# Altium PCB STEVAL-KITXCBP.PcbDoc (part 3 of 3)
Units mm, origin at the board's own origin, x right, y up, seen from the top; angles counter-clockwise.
Board outline 265 x 224 mm, 4 copper layers (Top Layer, GND, PWR, Bottom Layer), stack 1.55 mm thick; 241 components, 114 nets, 595 pads, 236 vias.
Unrouted connection lines stored in the file: 2.
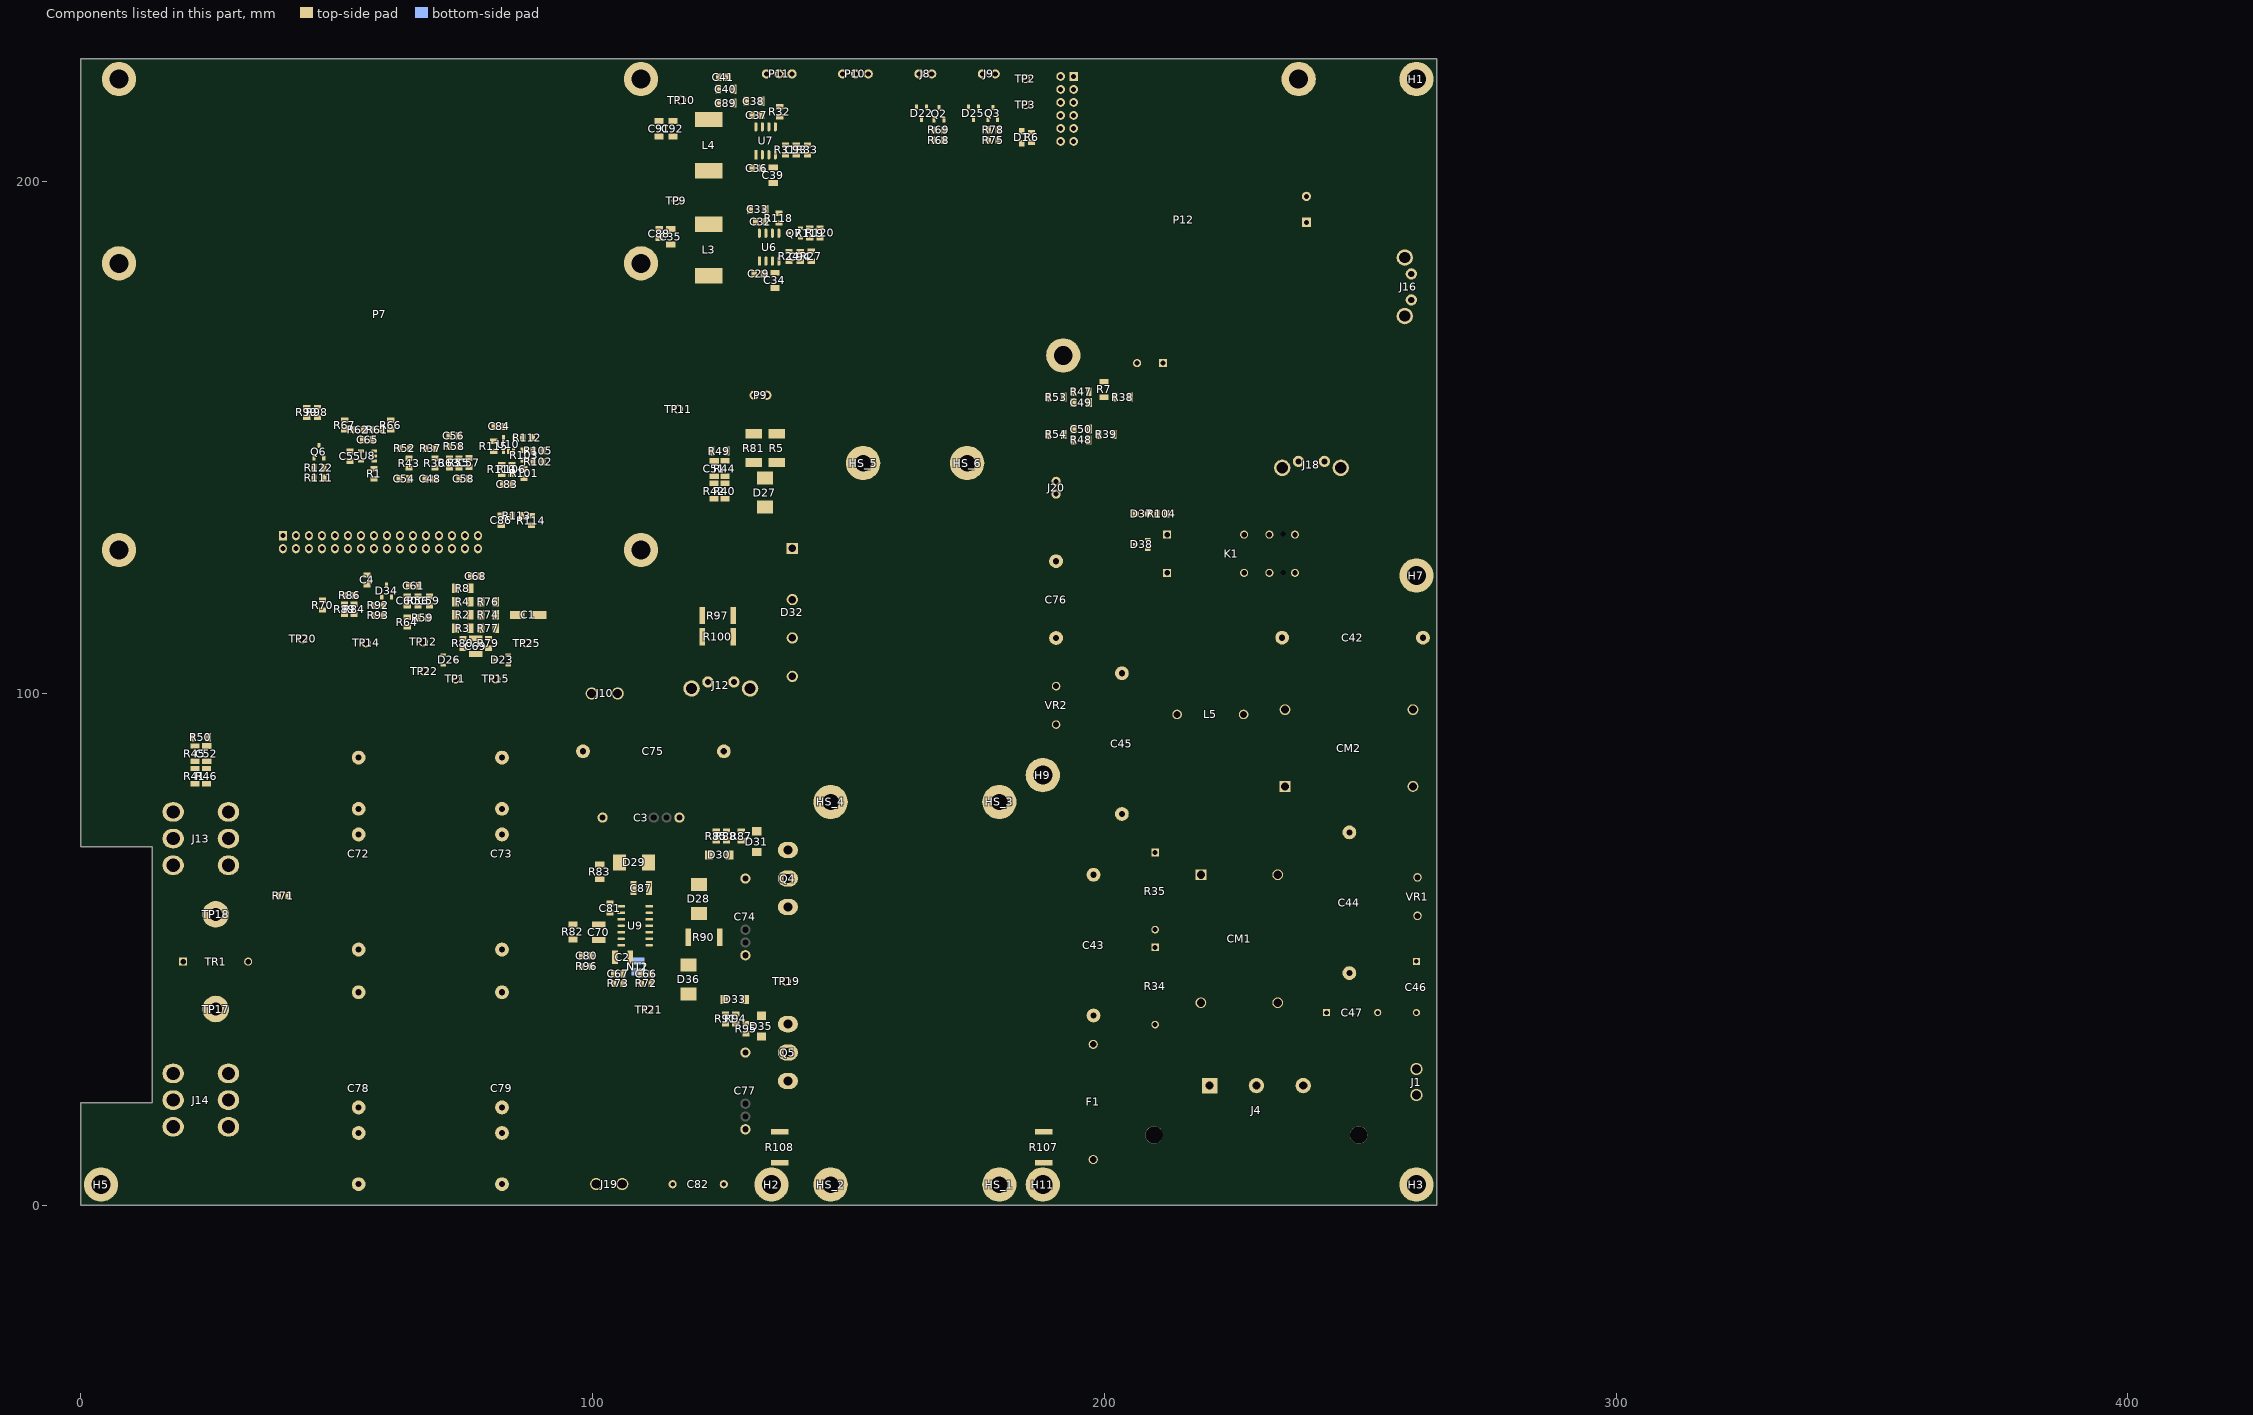
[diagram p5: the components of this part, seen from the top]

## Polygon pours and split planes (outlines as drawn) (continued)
+24V on Top Layer "TOP_LAYER_NONET_P-001" (solid, remove dead copper, pour order 199): 137.983,149.8 138.4,150.217 138.4,153.1 137.9,153.6 134.094,153.6 133.606,153.112 133.606,150.164 133.969,149.8 134.385,149.8
GND on Top Layer "TOP_LAYER_NONET_P-001" (solid, remove dead copper, pour order 197): 98.683,52.378 98.683,50.417 99.2,49.9 102.316,49.9 102.616,50.2 102.616,52.364 102.602,52.378
~Hbridge_ on Top Layer "TOP_LAYER_NONET_P-001" (solid, remove dead copper, pour order 196): 123.68,48.42 123.68,53.759 125.521,55.6 133.1,55.6 133.9,54.8 133.9,47.773 133.127,47 125.1,47
NetC44_2 on Top Layer "NETC44_2_L01_P151" (solid, remove dead copper, pour order 151): 248.339,32.667 249.944,34.272 249.944,39.904 251.077,41.037 255.983,41.037 256.626,41.658 256.626,59.946 258.506,61.826 263.281,61.826 263.942,62.486 263.942,85.245 263.332,85.854 253.88,85.854 251.851,83.825 251.851,69.598 246.06,63.807 231.023,48.77 231.023,33.947 232.304,32.667
~N_open on Top Layer "~N_OPEN_L01_P174" (solid, remove dead copper, pour order 174): 228.976,124.668 224.018,129.626 224.018,151.402 243.582,170.966 262.687,170.966 263.21,171.49 263.21,177.164 262.511,177.864 239.344,177.863 217.15,155.669 217.15,121.239 218.609,119.78 228.618,119.78 228.976,120.138
NetD27_1 on Top Layer "TOP_LAYER_NONET_P-001" (solid, remove dead copper, pour order 193): 129.3,146.7 129.3,141 129.55,140.75 137.95,140.75 138.2,141 138.2,146.7
~PGND on Top Layer "TOP_LAYER_NONET_P-001" (solid, remove dead copper, pour order 192): 115.776,43.2 122.7,43.2 122.9,43 122.9,38.7 122.3,38.1 116.1,38.1 115.6,38.6 115.6,43.024
~DCbus on Top Layer "TOP_LAYER_NONET_P-001" (solid, remove dead copper, pour order 191): 117.6,61.421 118.021,61 131.3,61 131.6,61.3 131.6,65.566 131.154,66.012 118.326,66.012 117.6,65.286
NetC87_1 on Top Layer "TOP_LAYER_NONET_P-001" (solid, remove dead copper, pour order 190): 120.9,44.5 121.3,44.9 121.3,53.759 123.141,55.6 124.1,56.559 124.1,59.406 124.006,59.5 117.8,59.5 114.902,56.602 113.802,56.602 113.249,56.049 113.249,55.651 113.8,55.1 114.652,55.1 116.2,53.552 116.2,44.9 116.6,44.5
~Cap on Top Layer "~CAP_L01_P166" (solid, remove dead copper, pour order 166): 84.5,29.1 86.766,31.366 86.766,50.597 84.379,52.984 51.467,52.984 31.119,32.743 31.105,32.743 28.619,30.256 17.843,30.256 15.08,27.493 15.08,12.789 17.861,10.008 37.107,10.008 56.199,29.1
NetD32_4 on Top Layer "NETD32_4_L01_P172" (solid, remove dead copper, pour order 172): 126,115.797 126,100 127.6,98.4 141.7,98.4 142.232,98.932 142.232,106.261 141.643,106.85 137.889,106.85 135.092,109.647 135.092,116.152 134.244,117 127.203,117
~Hbridge on Top Layer "~HBRIDGE_L01_P177" (solid, remove dead copper, pour order 177): 14.7,80 15.2,80.5 32.4,80.5 33.5,79.4 33.5,55.649 30.228,52.378 16.322,52.378 14.7,54
NetR34_1 on Top Layer "NETR34_1_L01_P161" (solid, remove dead copper, pour order 161): 208.062,56.34 207.858,56.136 207.858,47.978 208.038,47.798 211.892,47.798 211.973,47.878 211.973,56.11 211.743,56.34
~AC_N on Top Layer "~AC_N_L01_P157" (solid, remove dead copper, pour order 157): 187.013,70.8 219.712,70.8 221.219,69.294 221.219,60.754 220.182,59.718 202.319,59.718 193.076,50.475 193.076,28.4 195.514,25.961 223.139,25.961 223.5,25.6 223.5,18.5 223.24,18.24 188.47,18.24 184.643,22.067 184.643,68.43
~AC_L on Top Layer "~AC_L_L01_P150" (solid, remove dead copper, pour order 150): 205.037,39.779 196.886,39.779 195.788,38.681 195.788,30.112 196.891,29.009 203.845,29.009 220.451,29.009 221.778,30.335 221.778,41.404 221.016,42.166 216.444,42.166 214.056,39.779
no net on Top Overlay "TOP_LAYER_NONET_P-001" (hatched 45Degree grid 2.54 track 0.4): 142.98,0.017 142.98,150.017 182.98,150.017 182.98,0.017
GND on Bottom Layer "TOP_LAYER_NONET_P-001" (solid, remove dead copper, pour order 188): 199.6,222 198.145,223.455 4.355,223.455 1.5,220.6 1.5,95.1 3.8,92.8 28.2,92.8 35.1,85.9 35.1,61.178 41.278,55 85.93,55 100.13,40.8 112.638,40.8 113.005,41.167 113.005,45.716 112.621,46.1 104.476,46.1 103.657,46.919 103.657,50.976 104.435,51.754 106.684,51.754 107.954,53.024 107.954,58.843 102.197,64.6 50.85,64.6 48.7,66.75 48.7,95.9 50.4,97.6 79.4,97.6 121.984,140.184 153.395,140.184 199.6,186.389
~Neutral on Bottom Layer "~NEUTRAL_L04_P162" (solid, remove dead copper, pour order 162): 244.6,166.4 211.1,166.4 210.7,166 210.7,159.5 213.66,156.54 238.679,156.54 240.574,154.625 240.574,130.287 235.572,125.286 235.572,121.645 233.462,119.535 225.994,119.535 203.49,97.03 187.989,97.03 187.637,96.678 187.637,91.496 188.3,90.833 194.172,90.833 196.835,88.17 196.835,74.446 197.953,73.327 221.189,73.327 223.556,75.694 223.556,87.734 226.299,90.477 247.33,90.477 251.968,95.752 251.968,155.499 251.968,159.032
+24V on Bottom Layer "TOP_LAYER_NONET_P-001" (solid, remove dead copper, pour order 186): 109.7,208.8 106.1,205.2 70.3,205.2 39.53,174.43 39.53,131.095 40.493,130.132 40.915,129.71 40.915,127.253 39.262,125.6 33.276,125.6 28.5,130.376 28.5,176.7 67.4,215.6 108.8,215.6 109.7,214.7
+16V on Bottom Layer "+16V_L04_P170" (solid, remove dead copper, pour order 170): 140.411,194.361 140.411,203.51 139.499,204.368 70.668,204.368 40.28,173.98 40.28,123.897 40.492,123.7 48.09,123.7 49.073,124.683 49.073,165.132 69.518,185.776 138.871,185.776 139.192,186.097 139.192,193.142
~DCbus on Bottom Layer "~DCBUS_L04_P165" (solid, remove dead copper, pour order 165): 123.9,121 135.465,121 141.6,127.135 141.6,138 140.9,138.7 122.848,138.7 114.994,130.846 85.7,101.552 80.248,96.1 51.1,96.1 50.2,95.2 50.2,67.473 51.573,66.1 102.852,66.1 107.552,61.4 160.1,61.4 160.8,62.1 160.8,88.4 157.5,91.7 128.1,91.7 123.9,95.9
~PGND on Bottom Layer "TOP_LAYER_NONET_P-001" (solid, remove dead copper, pour order 189): 16.791,53.991 14,51.2 14,0.647 156.847,0.647 161.3,5.1 161.3,58.6 160.1,59.8 109.362,59.8 108.9,59.338 108.9,52.932 106.848,50.881 103.921,50.881 103.786,50.745 103.786,47.424 105.11,46.1 112.621,46.1 113.005,45.716 113.005,41.698 112.107,40.8 100.17,40.8 86.979,53.991
+16V on Bottom Layer "TOP_LAYER_NONET_P-001" (solid, remove dead copper, pour order 185): 96.3,53.508 96.3,50.308 95.976,49.984 94.324,49.984 93.947,50.362 93.947,53.455 94.3,53.808 96,53.808
NetC44_2 on Bottom Layer "NETC44_2_L04_P156" (solid, remove dead copper, pour order 156): 259.903,85.854 263.332,85.854 263.942,85.245 263.942,62.461 262.837,61.356 259.001,61.356 254.976,65.382 254.976,80.927
~AC_N on Bottom Layer "~AC_N_L04_P168" (solid, remove dead copper, pour order 168): 187.013,70.8 219.712,70.8 221.219,69.294 221.219,60.754 220.182,59.718 202.319,59.718 193.076,50.475 193.076,28.4 195.514,25.961 223.139,25.961 223.5,25.6 223.5,18.5 223.24,18.24 188.47,18.24 184.643,22.067 184.643,68.43
~AC_L on Bottom Layer "~AC_L_L04_P158" (solid, remove dead copper, pour order 158): 205.037,39.779 196.886,39.779 195.725,38.618 195.725,30.175 196.891,29.009 203.845,29.009 220.599,29.009 221.778,30.188 221.778,41.404 221.016,42.166 216.444,42.166 214.056,39.779
NetC44_1 on Bottom Layer "NETC44_1_L04_P155" (solid, remove dead copper, pour order 155): 230.922,85.753 230.414,85.245 230.414,56.594 232.446,54.562 251.953,54.562 255.356,51.158 255.356,44.13 256.304,43.182 263.281,43.182 264.163,44.064 264.163,60.03 263.789,60.404 258.072,60.404 251.953,66.523 251.953,83.619 249.768,85.804 249.718,85.753
NetC44_2 on Bottom Layer "NETC44_2_L04_P152" (solid, remove dead copper, pour order 152): 231.023,44.148 231.023,33.947 232.304,32.667 245.473,32.667 246.822,34.016 246.822,38.915 248.944,41.037 251.75,43.843 251.75,47.246 250.073,48.923 235.798,48.923
+24V on PWR "+24V_L03_P171" (solid, remove dead copper, pour order 171): 197.844,223.456 199.4,221.9 199.4,187.2 161.4,149.2 132.486,149.2 132.486,218.084 133.045,218.643 154.689,218.643 159.502,223.456
~Line on PWR "~LINE_L03_P164" (solid, remove dead copper, pour order 164): 200.33,106.682 203.075,109.428 203.075,128.989 203.075,165.275 204.1,166.3 207.1,166.3 207.1,161 218.177,149.923 239.777,149.923 240.574,149.126 240.574,129.067 239.899,128.393 232.193,128.393 217.612,113.812 217.612,92.204 215.631,90.223 210.094,90.223 202.677,97.64 188.961,97.64 187.894,98.707 187.894,105.463 189.113,106.682
+3V3 on PWR "TOP_LAYER_NONET_P-001" (solid, remove dead copper, pour order 183): 46.62,100.68 48.9,98.4 79.05,98.4 92.763,112.113 92.763,153.453 90.216,156 51.446,156 46.62,151.174
+5V on PWR "+5V_L03_P175" (solid, remove dead copper, pour order 175): 28.575,133.615 38.087,124.102 43.876,124.102 46.051,126.277 46.051,132.649 36.746,141.954 36.746,161.996 76.55,201.8 115.454,201.8 124.037,210.383 124.037,220.248 123.242,221.043 116.576,221.043 107.065,211.533 71.322,211.533 28.575,168.786
+3V3 on PWR "TOP_LAYER_NONET_P-001" (solid, remove dead copper, pour order 184): 131.73,220.232 133.318,218.643 151.62,218.643 152.034,219.058 152.034,222.9 151.465,223.469 133.232,223.469 131.73,221.967
~Hbridge_ on PWR "TOP_LAYER_NONET_P-001" (solid, remove dead copper, pour order 194): 22.5,45.1 20.831,43.431 20.831,32.369 22.2,31 30.154,31 33.3,27.854 33.3,21.6 36.934,17.966 149.066,17.966 152.2,21.1 152.2,56.4 148,60.6 125.6,60.6 122.311,57.311 122.311,41.168 118.243,37.1 98.5,37.1 90.5,45.1
~AC_N on PWR "~AC_N_L03_P167" (solid, remove dead copper, pour order 167): 187.013,70.8 219.712,70.8 221.219,69.294 221.219,60.754 220.182,59.718 202.319,59.718 193.076,50.475 193.076,28.4 195.514,25.961 223.139,25.961 223.5,25.6 223.5,18.5 223.24,18.24 188.47,18.24 184.643,22.067 184.643,68.43
~Line_pf on PWR "~LINE_PF_L03_P163" (solid, remove dead copper, pour order 163): 262.164,88.394 264.95,91.181 264.95,112.989 261.3,116.639 224.622,116.639 221.066,113.083 221.066,90.426 223.098,88.394
~AC_L on PWR "~AC_L_L03_P159" (solid, remove dead copper, pour order 159): 205.037,39.779 196.886,39.779 195.725,38.618 195.725,30.175 196.891,29.009 203.845,29.009 220.482,29.009 221.778,30.305 221.778,41.404 221.016,42.166 216.444,42.166 214.056,39.779
NetC44_2 on PWR "NETC44_2_L03_P154" (solid, remove dead copper, pour order 154): 248.339,32.667 249.944,34.272 249.944,39.904 251.077,41.037 255.983,41.037 256.626,41.658 256.626,59.946 258.506,61.826 263.281,61.826 263.942,62.486 263.942,85.245 263.332,85.854 253.88,85.854 251.851,83.825 251.851,69.598 246.06,63.807 231.023,48.77 231.023,33.947 232.304,32.667

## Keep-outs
GND:
  circle w0.1: c109.5,128 r4.4
  circle w0.1: c146.543,4 r4.45
Bottom Layer:
  lines w0.1: 106.578,124.71 cw(c109.5,128) 112.923,130.764
Keep-Out Layer:
  circle w0.1: c7.5,220 r4.45
  circle w0.1: c109.5,220 r4.45
  circle w0.1: c109.5,184 r4.45
  circle w0.1: c7.5,128 r4.45
  circle w0.1: c7.5,184 r4.45
  circle w0.1: c146.543,78.753 r4.45
  circle w0.1: c152.893,144.965 r4.45

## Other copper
Top Layer:
  rectangle net ~Hbridge_: 124.391,54 125.8,54.343
  rectangle net ~Hbridge_: 123.68,50.2 125.8,54.058
  rectangle net ~PGND: 116.7,39.5 120.9,43
  rectangle net NetC87_1: 116.8,45.2 120.8,48.6
  rectangle net NetC87_1: 117.8,50.2 119.7,54.4
  rectangle net NetC87_1: 118.8,55.3 122.8,58.7
  rectangle net ~DCbus: 118.8,61 122.8,64.3
  region net NetD32_4: 125.543,108.427 129.526,108.427 131.133,110.034 131.133,116.409 130.541,117 125.848,117 125.543,116.695
  pour cut-out: 132.819,183.324 132.819,183.093 132.799,183.073 132.875,183.073 132.916,183.114 132.916,183.139
  region: 416.329,194.47 416.329,194.267 416.126,194.267 416.126,194.47 416.126,194.673 416.329,194.673
  region net ~PGND: 123.601,118.532 120.228,118.532 118,116.304 118,108.258 118.569,107.688 123.601,107.688
  region net HS_2: 149.737,2.084 148.469,0.817 141.615,0.817 141,1.431 141,10.843 138.315,13.528 134.9,13.528 134.9,14.9 143.534,14.9 149.737,8.698
  region net PE03: 123.157,8.4 122.462,7.705 122.462,1.184 123.106,0.54 136.725,0.54 138.3,2.115 138.3,7.7 137.6,8.4
  region net HS_1: 176.06,1.473 176.718,0.815 182.532,0.815 182.791,1.074 182.791,11.269 184.895,13.374 189.848,13.374 189.848,14.846 179.776,14.846 176.06,11.13
  region net PE03: 186.198,8.782 184.904,7.489 184.904,1.791 186.018,0.677 190.082,0.677 191.129,1.725 191.129,7.607 189.955,8.782
  text ".layer_name" at 90.889,-24.229 h1.52
GND:
  rectangle net ~PGND: 106.379,47.113 111.74,49.372
  rectangle net GND: 106.379,44.252 112.621,46.1
  region net NetC76_2: 228.11,118.365 230.886,121.14 230.886,124.333 231.135,124.582 233.462,124.582 233.771,124.272 233.771,115.537 231.813,113.579 231.428,113.579 228.247,116.76
  text ".layer_name" at 91.625,-23.739 h1.52
PWR:
  text ".layer_name" at 91.872,-23.617 h1.52
Bottom Layer:
  rectangle net GND: 107.423,44.4 110.2,44.874
  rectangle net ~PGND: 106.023,47.113 112.621,48.9
  rectangle net GND: 106.023,44.4 112.621,46.1
  pour cut-out: 136.086,121 120.002,121 116.4,117.398 116.4,107.9 118.1,106.2 133.952,106.2 136.086,108.334 136.086,114.816
  region net +24V: 137.282,218.364 132.875,218.364 132.687,218.176 132.687,215.952 133.166,215.473 137.602,215.473 137.81,215.682 137.81,218.055 137.502,218.364
  region net NetC76_1: 226.979,137.724 225.323,137.724 225.323,141.303 227.676,143.655 229.458,143.655 233.771,139.341 233.771,130.241 233.462,129.931 231.135,129.931 230.886,130.18 230.886,133.817
  text ".layer_name" at 92.24,-24.354 h1.52

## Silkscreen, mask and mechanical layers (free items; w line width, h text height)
Top Overlay:
  drawing of 79 lines, arcs and shapes, not listed
  text "GND" at 142.469,220.1 h0.64 r90
  text "GND" at 195.434,219.972 h0.76
  text "+3V3" at 131.3,219.342 h0.64 r90
  text "+24V" at 195.434,217.382 h0.76
  text "GND" at 154.61,215 h0.76 r90
  text "+24V" at 195.434,214.842 h0.76
  text "+3V3" at 149.394,214.8 h0.64 r90
  text "GND" at 189.792,213.387 h0.76 r90
  text "+24V" at 195.434,212.302 h0.76
  text "+24V" at 195.434,209.812 h0.76
  text "GND" at 195.8,207.272 h0.76
  text "WARNING!" at 163.413,192.759 h2
  text "J" at 257,192.1 h15.24 r90
  text "STEVAL-KiTXCBP / STEVAL$KiTXCBPA" at 262.9,191.6 h2.6 r90
  text "HIGH VOLTAGE" at 162.065,191.073 h1.8
  text "ON BOARD" at 163.785,189.573 h1.8
  text "~L_OPEN" at 249.3,182.3 h0.76
  text "~N_OPEN" at 249.6,174.8 h0.76
  text "Temp. sensor" at 128.4,161.8 h0.76
  text "~LINE" at 207.08,156.893 h0.76 r90
  text "~NEUTRAL" at 212.16,155.742 h0.76 r90
  text "~LINE" at 238.4,150.4 h0.76 r90
  text "~NEUTRAL" at 243.6,150.3 h0.76 r90
  text "FOR EVALUATION ONLY" at 259.651,142.135 h1.14 r90
  text "NOT FCC APPROVED" at 261.548,142.135 h1.14 r90
  text "FOR RESALE" at 263.41,142.135 h1.14 r90
  text "I" at 262.2,136.4 h7.62 r90
  text "GND" at 42.333,132.534 h0.76
  text "TempSens2" at 63.098,132.455 h0.64 r90
  text "Heatsink" at 64.93,132.455 h0.64 r90
  text "Temp_p" at 65.948,132.451 h0.64 r90
  text "PWM_1L*" at 52.717,132.427 h0.64 r90
  text "pwm_en/SD*" at 55.169,132.441 h0.64 r90
  text "Zero-X" at 57.841,132.427 h0.76 r90
  text "GND" at 60.244,132.441 h0.76 r90
  text "PWM_1H" at 50.295,132.424 h0.64 r90
  text "UDCp" at 68.22,132.402 h0.64 r90
  text "IDCp" at 70.541,132.402 h0.64 r90
  text "IACp" at 73.081,132.402 h0.64 r90
  text "GND" at 78.161,132.402 h0.76 r90
  text "GND" at 75.391,132.272 h0.76 r90
  text "dge" at 68.496,124.892 h0.64 r90
  text "GND" at 75.621,124.691 h0.76 r90
  text "Fan1" at 49.805,124.577 h0.64 r90
  text "PWM" at 50.635,124.589 h0.64 r90
  text "GND" at 78.199,124.559 h0.76 r90
  text "Ubri" at 67.473,124.518 h0.64 r90
  text "IDCn" at 70.406,124.45 h0.64 r90
  text "En" at 58.682,124.435 h0.76 r90
  text "GND" at 60.6,124.435 h0.76 r90
  text "16V" at 57.752,124.402 h0.76 r90
  text "+24V" at 39.908,124.376 h0.64 r90
  text "PWM" at 53.383,124.389 h0.64 r90
  text "LINE" at 55.352,124.376 h0.64 r90
  text "Sen3" at 63.401,124.384 h0.64 r90
  text "Fan2" at 52.554,124.364 h0.64 r90
  text "Temp" at 62.657,124.319 h0.64 r90
  text "+16V" at 42.675,124.273 h0.64 r90
  text "+5V" at 45.212,124.273 h0.64 r90
  text "+3V3" at 47.752,124.273 h0.64 r90
  text "en" at 55.969,124.285 h0.64 r90
  text "Ucap" at 65.512,124.247 h0.64 r90
  text "IACn" at 73.132,124.227 h0.64 r90
  text "Ubridge" at 62,107.2 h0.76
  text "Zero-X" at 53.4,107.1 h0.76
  text "IDCp" at 62.7,102.5 h0.76
  text "DCbus" at 114.9,100.422 h0.76 r90
  text "DCbus" at 94.074,98.352 h0.76
  text "WARNING" at 133.63,81.723 h1.5
  text "WARNING" at 186.23,69.523 h1.5
  text "~Hbridge" at 29.723,55.107 h0.76
  text "~Hbridge_" at 30.379,36.525 h0.76
  text "PGND" at 109.576,35 h0.76
  text "~Cap" at 21.288,27.427 h0.76
  text "PE" at 257.297,22.215 h0.76
  text "PGND" at 101.674,5.812 h0.76
  text "PGND" at 117.307,3.32 h0.76
  text ".layer_name" at 91.633,-22.735 h1.52
Bottom Overlay:
  text ".layer_name" at 91.981,-22.824 h1.52
Top Paste:
  text ".layer_name" at 92.332,-22.651 h1.52
Bottom Paste:
  text ".layer_name" at 92.098,-22.904 h1.52
Top Solder:
  text ".layer_name" at 92.565,-22.651 h1.52
Bottom Solder:
  text ".layer_name" at 92.098,-22.904 h1.52
Drill Guide:
  text ".layer_name" at 92.019,-23.059 h1.52
M1 Board Outline:
  lines w0.1: 170.037,217.6 175.037,217.6
  lines w0.254: 0,0 0,20 14,20 14,70 0,70 0,224 265,224 265,0 0,0
  text ".layer_name" at 91.638,-22.78 h1.52
M2 Board Dimensions:
  text ".layer_name" at 92.001,-22.833 h1.52
M9 Title Sheet:
  lines w0.2: 83.259,281.275 113.009,281.275 ; 229.495,261.582 262.995,261.582 ; 82.259,249.275 227.009,249.275 227.009,284.775 220.759,284.775 82.259,284.775 82.259,255.525 82.259,249.275 ; 83.009,250.525 85.509,250.525 85.509,253.025 83.009,253.025 83.009,250.525 ; 83.009,259.525 85.509,259.525 85.509,262.025 83.009,262.025 83.009,259.525 ; 121.508,256.179 124.008,256.179 124.008,258.679 121.508,258.679 121.508,256.179 ; 121.509,259.525 124.009,259.525 124.009,262.025 121.509,262.025 121.509,259.525 ; 121.509,262.525 124.009,262.525 124.009,265.025 121.509,265.025 121.509,262.525 ; 121.509,265.525 124.009,265.525 124.009,268.025 121.509,268.025 121.509,265.525 ; 121.509,268.525 124.009,268.525 124.009,271.025 121.509,271.025 121.509,268.525 ; 121.509,271.525 124.009,271.525 124.009,274.025 121.509,274.025 121.509,271.525 ; 138.008,256.179 140.508,256.179 140.508,258.679 138.008,258.679 138.008,256.179 ; 138.009,259.525 140.509,259.525 140.509,262.025 138.009,262.025 138.009,259.525 ; 138.009,262.525 140.509,262.525 140.509,265.025 138.009,265.025 138.009,262.525 ; 138.009,265.525 140.509,265.525 140.509,268.025 138.009,268.025 138.009,265.525 ; 138.009,268.525 140.509,268.525 140.509,271.025 138.009,271.025 138.009,268.525 ; 138.009,271.525 140.509,271.525 140.509,274.025 138.009,274.025 138.009,271.525 ; 156.259,268.525 158.759,268.525 158.759,271.025 156.259,271.025 156.259,268.525 ; 156.259,271.525 158.759,271.525 158.759,274.025 156.259,274.025 156.259,271.525 ; 172.259,262.525 174.759,262.525 174.759,265.025 172.259,265.025 172.259,262.525 ; 172.259,265.525 174.759,265.525 174.759,268.025 172.259,268.025 172.259,265.525 ; 172.259,268.525 174.759,268.525 174.759,271.025 172.259,271.025 172.259,268.525 ; 172.259,271.525 174.759,271.525 174.759,274.025 172.259,274.025 172.259,271.525 ; 229.495,249.607 262.995,249.607 262.995,265.582 229.495,265.582 229.495,249.607
  text "PCB SPECIFICATIONS :" at 83.259,281.775 h3
  text "A.   MATERIAL :" at 83.259,277.775 h3
  text "FR-4 HIGH TG" at 121.759,277.775 h3
  text "B.   MATERIAL FAMILY :" at 83.259,274.775 h3
  text "N/A" at 121.759,274.775 h3
  text "x   GREEN" at 121.959,272.008 h3
  text "WHITE" at 141.687,271.827 h3
  text "C.   SOLDERMASK COLOR :" at 83.259,271.775 h3
  text "BLUE" at 156.509,271.775 h3
  text "BLACK" at 172.509,271.775 h3
  text "D.   SILKSCREEN COLOR :" at 83.259,268.775 h3
  text "X  WHITE" at 121.759,268.775 h3
  text "YELLOW" at 138.259,268.775 h3
  text "BLACK" at 156.509,268.775 h3
  text "Blue ink PANTONE 2955" at 172.509,268.775 h3
  text "E.   SURFACE FINISH :" at 83.259,265.775 h3
  text "X  ENIG" at 121.759,265.775 h3
  text "IMMERSION SILVER" at 138.259,265.775 h3
  text "IMMERSION TIN" at 172.509,265.775 h3
  text "HASL" at 121.759,262.775 h3
  text "HASL (PB-FREE)" at 138.259,262.775 h3
  text "GOLDEN FINGER" at 172.509,262.775 h3
  text "MINIMUM PARAMETERS" at 230.745,262.332 h3
  text "F.   IMPEDANCE CONTROL :" at 83.259,259.775 h3
  text "X  NO" at 121.759,259.775 h3
  text "YES  (SEE IMPEDANCE TABLE FOR DETAIL INFORMATION)" at 138.259,259.775 h3
  text "DEFAULT" at 230.745,256.832 h3
  text "G.   VIA TENTING :" at 83.259,256.775 h3
  text "YES" at 141.263,256.54 h3
  text "X  NO" at 121.86,256.397 h3
  text "TRACKS : 0.381mm           /  GAPS     : 0.229mm" at 230.745,251.082 h3
  text "H.   STACK-UP :" at 83.259,250.775 h3
  text "SEE LAYER STACK-UP SEQUENCE FOR OVERALL THICKNESS." at 121.759,250.775 h3
  text ".layer_name" at 91.948,-22.833 h1.52
M10 Fab Notes:
  text "FAB NOTES:" at 276.007,49.398 h1.27
  text "1) ALL CORE AND PREPREG THICKNESSES ARE UP TO FAB SHOP TO SELECT." at 282.913,45.857 h1.27
  text "2)ALL VIAS ARE  NON TENTED" at 282.913,43.132 h1.27
  text "3)VENDOR MAY ADJUST SOLDERMASK WHEREVER SOLDERMASK PADS ARE SAME SIZE(1:1)" at 282.913,40.611 h1.27
  text "AS PER MANUFACTURING CAPABILITIES AND ALL OTHER SOLDERMASK PADS SHALL NOT BE MODIFIED" at 285.394,37.741 h1.27
  text "PROVIDED NO ADJACENT COPPER IS EXPOSED AND NO CONFLICT PRODUCED WITH ANY STATED" at 285.394,35.176 h1.27
  text "\"VIA TENTING/COVERING\" REQUIREMENTS." at 285.394,32.813 h1.27
  text "4)THIS IS NOT AN IMPEDANCE CONTROLLED BOARD" at 282.913,29.816 h1.27
  text "5)BOARD THICKNESS IS 1.6MM +/- 10% TOLERANCE" at 282.913,27.636 h1.27
  text "6)ALL FABRICATION ITEM MUST MEET OR EXCEED BEST INDUSTRY PRACTICE. IPC-A-600C (Commercial Std.)" at 282.913,25.456 h1.27
  text "7)MINIMUM COPPER WALL THICKNESS OF PLATED-THRU   HOLES TO BE 0.001 INCH, WITH A MINIMUM ANNULAR RING OF 0.002 INCH" at 282.913,23.275 h1.27
  text "8)MAX. WARP & TWIST TO BE .0075 INCHES PER INCH" at 282.913,21.095 h1.27
  text "9)HOLE POSITIONAL TOLERANCE ACCURACY IS  +/- 3 MILS" at 282.913,18.915 h1.27
  text "10)SOLDERMASK BOTH SIDES PER ARTWORK.GREEN LPI" at 282.913,16.734 h1.27
  text "11)SILKSCREEN BOTH SIDES PER ARTWORK.COLOR=WHITE." at 282.913,14.757 h1.27
  text "12)DIELECTRIC MATERIAL: FR4-HIGH TG" at 282.913,12.634 h1.27
  text ".layer_name" at 92.311,-22.833 h1.52
M11 Gerber Information:
  circle w0.254: c169.089,-30.052 r1.3
  region: 154.611,-31.146 143.855,-31.146 144.848,-28.653 152.706,-28.653 153.154,-27.893 155.363,-30.442
  region: 168.614,-22.816 153.087,-22.816 152.392,-24.591 151.182,-25.816 149.785,-23.956 149.785,-22.305 150.928,-20.908 152.364,-20.53 168.614,-20.53
  lines w0.254: 144.848,-28.653 153.64,-28.653 150.574,-25.115 cw(c152.378,-23.171) 152.618,-20.53 169.382,-20.53 168.62,-22.816 ; 148.162,-20.283 cw(c150.588,-21.253) 150.824,-18.651 ; 148.201,-20.25 143.855,-31.146 163.177,-31.146 ccw(c163.426,-28.411) 165.975,-29.431 ; 149.941,-24.185 155.363,-30.442 ; 150.195,-24.185 155.5,-30.306 ; 150.195,-23.931 155.5,-30.052 ; 150.293,-22.816 163.286,-22.816 ; 150.322,-23.804 155.627,-29.925 ; 150.449,-23.677 155.754,-29.798 ; 150.576,-23.55 155.881,-29.671 ; 150.703,-23.423 156.008,-29.544 ; 150.757,-21.471 156.062,-27.592 ; 150.826,-18.651 170.275,-18.651 165.976,-29.428 ; 150.83,-23.296 156.08,-29.354 ; 150.83,-23.042 156.135,-29.163 ; 150.83,-22.788 156.135,-28.909 ; 150.83,-21.899 156.135,-28.02 ; 150.957,-22.661 156.262,-28.782 ; 150.957,-22.28 156.262,-28.401 ; 152.328,-28.666 ccw(c152.433,-28.131) 152.731,-27.674 ; 153.415,-22.803 ccw(c153.389,-23.37) 153.059,-23.832 155.423,-26.561 cw(c153.62,-28.505) 154.352,-31.053 ; 159.696,-30.941 162.586,-22.562 ; 159.919,-30.892 162.788,-22.571 ; 160.046,-30.892 162.915,-22.571 ; 160.3,-30.892 163.169,-22.571 ; 160.554,-30.892 163.423,-22.571 ; 160.808,-30.892 163.677,-22.571 ; 161.062,-30.892 163.931,-22.571 ; 161.316,-30.892 164.185,-22.571 ; 161.57,-30.892 164.439,-22.571 ; 161.824,-30.892 164.693,-22.571 ; 162.032,-30.941 164.922,-22.562 ; 164.922,-22.816 168.614,-22.816 ; 167.946,-22.813 168.708,-20.527 ; 168.112,-22.816 168.874,-20.53 ; 168.366,-22.816 169.128,-20.53
  lines w0.3: 82.084,-35.032 172.084,-35.032 172.084,-15.032 82.084,-15.032 ; 82.084,-30.032 142.084,-30.032 ; 82.084,-25.032 142.084,-25.032 ; 82.084,-20.032 142.084,-20.032 ; 82.085,-35.032 82.085,-15.032 ; 122.084,-35.032 122.084,-20.032 ; 142.084,-35.032 142.084,-15.032 ; 159.696,-30.941 162.032,-30.941
  text "Project: POWER STAGE BOARD" at 83.085,-18.248 h3
  text "Layer:" at 83.085,-23.332 h3
  text ".layer_name" at 90.302,-23.381 h1.52
  text "Variant: '.VariantName'" at 83.085,-28.332 h3
  text "R" at 168.581,-30.814 h1.52
  text "YEAR: 2022" at 83.085,-33.332 h3
  text "Rev: A" at 123.143,-33.332 h3
M12 Stackup:
  drawing of 307 lines, arcs and shapes, not listed
  text "Layer" at 285.381,217.978 h1.52
  text "Name" at 295.793,217.978 h1.52
  text "Material" at 319.408,217.978 h1.52
  text "Thickness" at 341.246,217.978 h1.52
  text "Constant" at 357.752,217.978 h1.52
  text "Board Layer Stack" at 372.227,217.978 h1.52
  text "Top Overlay" at 295.793,214.93 h1.52
  text "Top Solder" at 295.793,211.882 h1.52
  text "Solder Resist" at 319.408,211.882 h1.52
  text "0.40mil" at 341.246,211.882 h1.52
  text "3.5" at 357.752,211.882 h1.52
  text "1" at 285.381,208.834 h1.52
  text "Top Layer" at 295.793,208.834 h1.52
  text "COPPER" at 319.408,208.834 h1.52
  text "2.76mil" at 341.246,208.834 h1.52
  text "2oz(70um)" at 407.837,208.845 h1.27
  text "Dielectric 1" at 295.793,205.786 h1.52
  text "FR-4 HIGH TG" at 319.408,205.786 h1.52
  text "15.00mil" at 341.246,205.786 h1.52
  text "4.2" at 357.752,205.786 h1.52
  text "2" at 285.381,202.738 h1.52
  text "GND" at 295.793,202.738 h1.52
  text "COPPER" at 319.408,202.738 h1.52
  text "2.76mil" at 341.246,202.738 h1.52
  text "2oz(70um)" at 407.655,202.326 h1.27
  text "Dielectric 2" at 295.793,199.69 h1.52
  text "FR-4 HIGH TG" at 319.408,199.69 h1.52
  text "20.00mil" at 341.246,199.69 h1.52
  text "4.2" at 357.752,199.69 h1.52
  text "3" at 285.381,196.642 h1.52
  text "PWR" at 295.793,196.642 h1.52
  text "COPPER" at 319.408,196.642 h1.52
  text "2.76mil" at 341.246,196.642 h1.52
  text "2oz(70um)" at 407.837,195.855 h1.27
  text "Dielectric 3" at 295.793,193.594 h1.52
  text "FR-4 HIGH TG" at 319.408,193.594 h1.52
  text "15.00mil" at 341.246,193.594 h1.52
  text "4.2" at 357.752,193.594 h1.52
  text "4" at 285.381,190.546 h1.52
  text "Bottom Layer" at 295.793,190.546 h1.52
  text "COPPER" at 319.408,190.546 h1.52
  text "2.76mil" at 341.246,190.546 h1.52
  text "2oz(70um)" at 407.837,190.316 h1.27
  text "Bottom Solder" at 295.793,187.498 h1.52
  text "Solder Resist" at 319.408,187.498 h1.52
  text "0.40mil" at 341.246,187.498 h1.52
  text "3.5" at 357.752,187.498 h1.52
  text "Bottom Overlay" at 295.793,184.45 h1.52
  text "COPPER THICKNESS: FINISHED" at 284.079,181.494 h1.27
  text ".layer_name" at 91.328,-22.475 h1.52
Drill Drawing:
  circle w0.254: c287.005,118.173 r0.508
  circle w0.254: c287.005,118.173 r0.847
  circle w0.254: c287.005,72.453 r0.847
  lines w0.254: 286.159,76.263 287.005,75.416 287.852,76.263 287.005,77.11 286.159,76.263 ; 286.159,80.92 287.852,80.92 287.005,79.226 286.159,80.92 ; 286.159,83.46 286.582,83.46 287.005,83.036 287.429,83.46 287.852,83.46 287.429,83.883 287.852,84.306 287.429,84.306 287.005,84.73 286.582,84.306 286.159,84.306 286.582,83.883 286.159,83.46 ; 286.159,90.656 287.005,91.08 287.852,90.656 287.429,91.503 287.852,92.35 287.005,91.926 286.159,92.35 286.582,91.503 286.159,90.656 ; 286.159,94.466 287.852,94.466 287.852,96.16 286.159,96.16 286.159,94.466 ; 286.159,105.896 287.852,105.896 287.852,107.59 286.159,107.59 286.159,105.896 ; 286.159,113.516 287.005,113.94 287.852,113.516 287.429,114.363 287.852,115.21 287.005,114.786 286.159,115.21 286.582,114.363 286.159,113.516 ; 286.159,144.42 286.582,144.42 287.005,143.996 287.429,144.42 287.852,144.42 287.429,144.843 287.852,145.266 287.429,145.266 287.005,145.69 286.582,145.266 286.159,145.266 286.582,144.843 286.159,144.42 ; 286.159,148.23 286.582,148.23 286.582,147.806 287.429,147.806 287.429,148.23 287.852,148.23 287.852,149.076 287.429,149.076 287.429,149.5 286.582,149.5 286.582,149.076 286.159,149.076 286.159,148.23 ; 286.159,166.856 286.159,167.28 286.582,167.703 286.159,168.126 286.159,168.55 286.582,168.55 287.005,168.126 287.429,168.55 287.852,168.55 287.852,168.126 287.429,167.703 287.852,167.28 287.852,166.856 287.429,166.856 287.005,167.28 286.582,166.856 286.159,166.856 ; 286.159,172.36 287.852,172.36 287.005,170.666 286.159,172.36 ; 286.497,80.581 287.513,80.581 287.005,79.565 286.497,80.581 ; 286.497,106.235 287.513,106.235 287.513,107.251 286.497,107.251 286.497,106.235 ; 286.497,113.855 287.005,114.109 287.513,113.855 287.259,114.363 287.513,114.871 287.005,114.617 286.497,114.871 286.751,114.363 286.497,113.855 ; 286.497,144.589 286.751,144.589 287.005,144.335 287.259,144.589 287.513,144.589 287.259,144.843 287.513,145.097 287.259,145.097 287.005,145.351 286.751,145.097 286.497,145.097 286.751,144.843 286.497,144.589 ; 286.497,148.399 286.751,148.399 286.751,148.145 287.259,148.145 287.259,148.399 287.513,148.399 287.513,148.907 287.259,148.907 287.259,149.161 286.751,149.161 286.751,148.907 286.497,148.907 286.497,148.399
  lines w0.381: 284.64,70.463 372.044,70.463 ; 284.64,173.333 372.044,173.333 ; 298.632,66.653 298.632,177.143 ; 313.868,66.653 313.868,177.143 ; 343.07,66.653 343.07,177.143 ; 355.919,66.653 355.919,177.143 ; 284.64,66.653 372.044,66.653 372.044,177.143 284.64,177.143 284.64,66.653
  text "Symbol" at 286.926,174.476 h1.83
  text "Count" at 299.775,174.476 h1.83
  text "Hole Size" at 315.011,174.476 h1.83
  text "Plated" at 344.213,174.476 h1.83
  text "Via/Pad" at 357.062,174.476 h1.83
  text "2" at 299.775,170.666 h1.52
  text "11.81mil (0.300mm)" at 315.011,170.666 h1.52
  text "PTH" at 344.213,170.666 h1.52
  text "Via" at 357.062,170.666 h1.52
  text "2" at 299.775,166.856 h1.52
  text "39.37mil (1.000mm)" at 315.011,166.856 h1.52
  text "NPTH" at 344.213,166.856 h1.52
  text "Pad" at 357.062,166.856 h1.52
  text "2" at 299.775,163.046 h1.52
  text "42.00mil (1.067mm)" at 315.011,163.046 h1.52
  text "PTH" at 344.213,163.046 h1.52
  text "Pad" at 357.062,163.046 h1.52
  text "D" at 286.187,162.792 h1.69
  text "2" at 299.775,159.236 h1.52
  text "51.18mil (1.300mm)" at 315.011,159.236 h1.52
  text "PTH" at 344.213,159.236 h1.52
  text "Pad" at 357.062,159.236 h1.52
  text "I" at 286.469,158.982 h1.69
  text "2" at 299.775,155.426 h1.52
  text "53.31mil (1.354mm)" at 315.011,155.426 h1.52
  text "PTH" at 344.213,155.426 h1.52
  text "Pad" at 357.062,155.426 h1.52
  text "C" at 286.187,155.172 h1.69
  text "2" at 299.775,151.616 h1.52
  text "98.43mil (2.500mm)" at 315.011,151.616 h1.52
  text "PTH" at 344.213,151.616 h1.52
  text "Pad" at 357.062,151.616 h1.52
  text "Q" at 286.187,151.362 h1.69
  text "2" at 299.775,147.806 h1.52
  text "133.86mil (3.400mm)" at 315.011,147.806 h1.52
  text "PTH" at 344.213,147.806 h1.52
  text "Pad" at 357.062,147.806 h1.52
  text "3" at 299.775,143.996 h1.52
  text "51.18mil (1.300mm)" at 315.011,143.996 h1.52
  text "PTH" at 344.213,143.996 h1.52
  text "Pad" at 357.062,143.996 h1.52
  text "3" at 299.775,140.186 h1.52
  text "62.99mil (1.600mm)" at 315.011,140.186 h1.52
  text "PTH" at 344.213,140.186 h1.52
  text "Pad" at 357.062,140.186 h1.52
  text "A" at 286.187,139.932 h1.69
  text "4" at 299.775,136.376 h1.52
  text "38.74mil (0.984mm)" at 315.011,136.376 h1.52
  text "PTH" at 344.213,136.376 h1.52
  text "Pad" at 357.062,136.376 h1.52
  text "E" at 286.187,136.122 h1.69
  text "4" at 299.775,132.566 h1.52
  text "45.43mil (1.154mm)" at 315.011,132.566 h1.52
  text "PTH" at 344.213,132.566 h1.52
  text "Pad" at 357.062,132.566 h1.52
  text "H" at 286.187,132.312 h1.69
  text "_" at 286.187,129.349 h1.69
  text "4" at 299.775,128.756 h1.52
  text "57.87mil (1.470mm)" at 315.011,128.756 h1.52
  text "PTH" at 344.213,128.756 h1.52
  text "Pad" at 357.062,128.756 h1.52
  text "6" at 299.775,124.946 h1.52
  text "35.59mil (0.904mm)" at 315.011,124.946 h1.52
  text "PTH" at 344.213,124.946 h1.52
  text "Pad" at 357.062,124.946 h1.52
  text "G" at 286.187,124.692 h1.69
  text "6" at 299.775,121.136 h1.52
  text "70.05mil (1.779mm)" at 315.011,121.136 h1.52
  text "PTH" at 344.213,121.136 h1.52
  text "Pad" at 357.062,121.136 h1.52
  text "P" at 286.187,120.882 h1.69
  text "6" at 299.775,117.326 h1.52
  text "70.08mil (1.780mm)" at 315.011,117.326 h1.52
  text "PTH" at 344.213,117.326 h1.52
  text "Pad" at 357.062,117.326 h1.52
  text "6" at 299.775,113.516 h1.52
  text "86.61mil (2.200mm)" at 315.011,113.516 h1.52
  text "PTH" at 344.213,113.516 h1.52
  text "Pad" at 357.062,113.516 h1.52
  text "`" at 286.469,110.017 h1.69
  text "6" at 299.775,109.706 h1.52
  text "125.98mil (3.200mm)" at 315.011,109.706 h1.52
  text "PTH" at 344.213,109.706 h1.52
  text "Pad" at 357.062,109.706 h1.52
  text "7" at 299.775,105.896 h1.52
  text "145.67mil (3.700mm)" at 315.011,105.896 h1.52
  text "PTH" at 344.213,105.896 h1.52
  text "Pad" at 357.062,105.896 h1.52
  text "8" at 299.775,102.086 h1.52
  text "42.00mil (1.067mm)" at 315.011,102.086 h1.52
  text "PTH" at 344.213,102.086 h1.52
  text "Pad" at 357.062,102.086 h1.52
  text "F" at 286.187,101.832 h1.69
  text "8" at 299.775,98.276 h1.52
  text "62.99mil (1.600mm)" at 315.011,98.276 h1.52
  text "PTH" at 344.213,98.276 h1.52
  text "Pad" at 357.062,98.276 h1.52
  text "B" at 286.187,98.022 h1.69
  text "8" at 299.775,94.466 h1.52
  text "145.67mil (3.700mm)" at 315.011,94.466 h1.52
  text "NPTH" at 344.213,94.466 h1.52
  text "Pad" at 357.062,94.466 h1.52
  text "11" at 299.775,90.656 h1.52
  text "51.18mil (1.300mm)" at 315.011,90.656 h1.52
  text "PTH" at 344.213,90.656 h1.52
  text "Pad" at 357.062,90.656 h1.52
  text "12" at 299.775,86.846 h1.52
  text "101.18mil (2.570mm)" at 315.011,86.846 h1.52
  text "PTH" at 344.213,86.846 h1.52
  text "Pad" at 357.062,86.846 h1.52
  text "J" at 286.187,86.592 h1.69
  text "14" at 299.775,83.036 h1.52
  text "47.24mil (1.200mm)" at 315.011,83.036 h1.52
  text "PTH" at 344.213,83.036 h1.52
  text "Pad" at 357.062,83.036 h1.52
  text "32" at 299.775,79.226 h1.52
  text "47.24mil (1.200mm)" at 315.011,79.226 h1.52
  text "PTH" at 344.213,79.226 h1.52
  text "Pad" at 357.062,79.226 h1.52
  text "62" at 299.775,75.416 h1.52
  text "39.37mil (1.000mm)" at 315.011,75.416 h1.52
  text "PTH" at 344.213,75.416 h1.52
  text "Pad" at 357.062,75.416 h1.52
  text "234" at 299.775,71.606 h1.52
  text "15.75mil (0.400mm)" at 315.011,71.606 h1.52
  text "PTH" at 344.213,71.606 h1.52
  text "Via" at 357.062,71.606 h1.52
  text "458 Total" at 299.775,67.796 h1.52
  text "DRILL TOLERANCE:" at 374.891,65.682 h1.52
  text "Slot definitions :" at 286.926,64.114 h1.52
  text "Routed Path Length" at 313.156,64.114 h1.52
  text "= Calculated from tool start centre position to tool end centre position." at 341.164,64.114 h1.52
  text "FOR PTH DRILL +/-3MIL" at 375.224,62.006 h1.52
  text "Hole Length" at 313.156,61.575 h1.52
  text "= Routed Path Length + Tool Size = Slot length as defined in the PCB layout" at 330.753,61.575 h1.52
  text "FOR NPTH DRILL +/-2MIL" at 375.224,59.192 h1.52
  text ".layer_name" at 92.159,-22.469 h1.52

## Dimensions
0,70 to 0,224 on M2 Board Dimensions
0,20 to 0,0 on M2 Board Dimensions
0,20 to 0,70 on M2 Board Dimensions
